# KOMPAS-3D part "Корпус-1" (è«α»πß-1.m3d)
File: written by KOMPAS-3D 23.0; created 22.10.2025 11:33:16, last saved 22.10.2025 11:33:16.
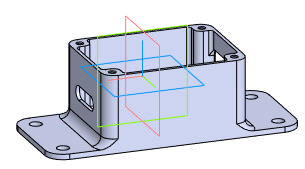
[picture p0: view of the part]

Document properties: Автор: ARM_513_VVK; Полное имя файла: F:\Демо\Демо вариант космос\Корпус-1.m3d

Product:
- Part/product: Корпус-1

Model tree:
1. Операция без истории:1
